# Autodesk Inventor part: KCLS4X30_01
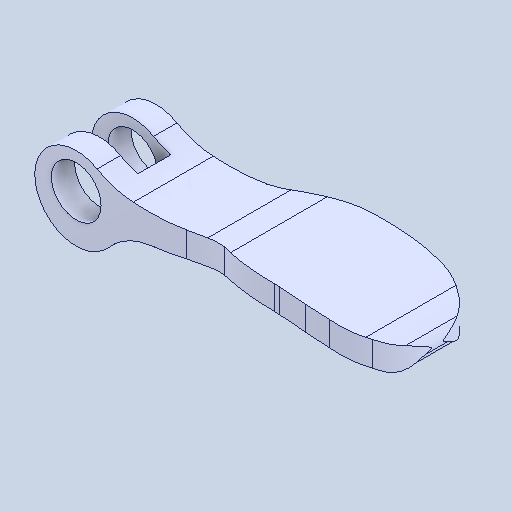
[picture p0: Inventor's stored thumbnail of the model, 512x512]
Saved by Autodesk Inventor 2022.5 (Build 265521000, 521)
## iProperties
Created: 2024-08
Part Number: KCLS4X30_01
Material: 一般
Document SubType Name: Modeling
Designer: ImaoCorp
Density: 1 g/cm^3
Appearance: 既定
Author: ImaoCorp
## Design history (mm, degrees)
feature "KCLS4X30_01"
node "ソリッド1"
